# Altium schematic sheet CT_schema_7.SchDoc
size 226 x 144 mm
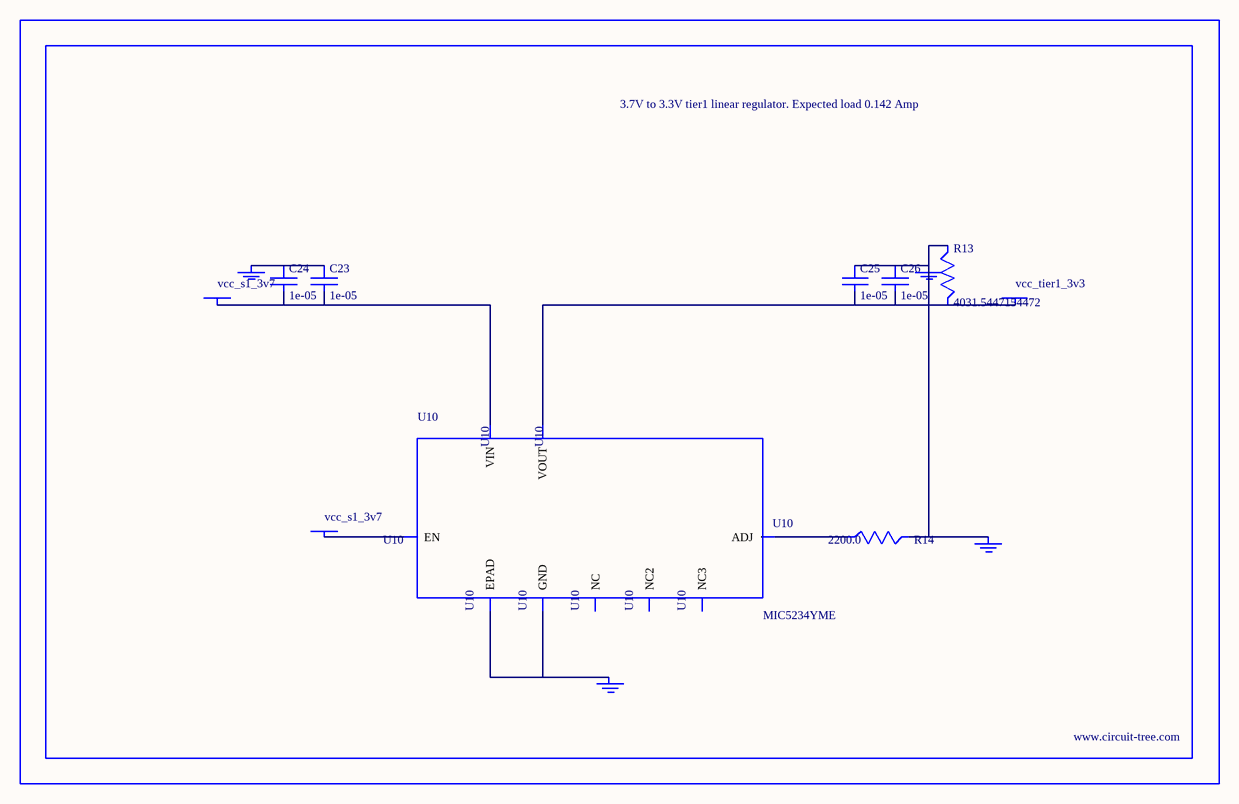
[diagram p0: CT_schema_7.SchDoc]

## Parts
BORDER6  (no value)
C23  1e-05  [C1210]
C24  1e-05  [C1210]
C25  1e-05  [C1210]
C26  1e-05  [C1210]
GND_INSTANCE_6_0  (no value)
GND_INSTANCE_6_1  (no value)
GND_INSTANCE_6_2  (no value)
GND_INSTANCE_6_3  (no value)
POWER_INSTANCE_6_0  vcc_tier1_3v3
POWER_INSTANCE_6_1  vcc_s1_3v7
POWER_INSTANCE_6_2  vcc_s1_3v7
R13  4031.5447154472  [R0603]
R14  2200.0  [R0603]
U10  MIC5234YME  [SOIC-8_EP]

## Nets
NetC23_1: C23.1 C24.1 GND_INSTANCE_6_3.0(GND)
NetC23_2: C23.2 C24.2 POWER_INSTANCE_6_2.0(PWR) U10.8(VIN)
NetC25_1: C25.1 C26.1 GND_INSTANCE_6_0.0(GND) GND_INSTANCE_6_1.0(GND) R13.1 R14.2
NetC25_2: C25.2 C26.2 POWER_INSTANCE_6_0.0(PWR) R13.2 U10.1(VOUT)
NetGND_INSTANCE_6_2_0: GND_INSTANCE_6_2.0(GND) U10.7(GND) U10.EPAD
NetPOWER_INSTANCE_6_1_0: POWER_INSTANCE_6_1.0(PWR) U10.5(EN)
NetR14_1: R14.1 U10.4(ADJ)

Not connected (* = marked no-connect by the designer): U10 2(NC) 3(NC2) 6(NC3)

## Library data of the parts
BORDER6 = BORDER_PAGE6
C23-C26 = C1210C106K5PACTU
GND_INSTANCE_6_0-GND_INSTANCE_6_3 = GND
POWER_INSTANCE_6_0-POWER_INSTANCE_6_2 = PWR
R13 = R13
R14 = RC0603JR-072K2L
